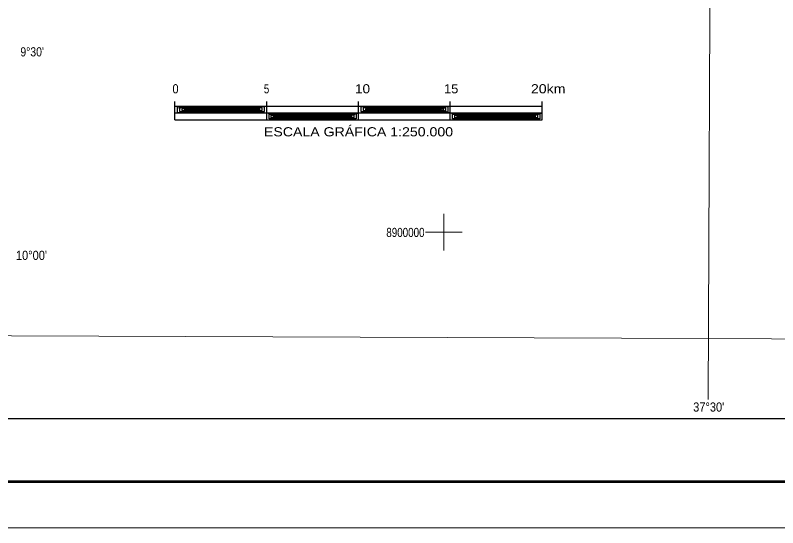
# Model space of a CAD drawing. Extents: x 553962 to 842807, y 8883888 to 9032388.
# Drawn here: x 626649 to 668185, y 8883888 to 8911837 of the extents above; entities that cross this region are included whole.
import ezdxf
from ezdxf.enums import TextEntityAlignment as Align

# ---------------------------------------------------------------- set-up
doc = ezdxf.new("R2010")
doc.units = 0
doc.header["$LTSCALE"] = 150
doc.header["$PDMODE"] = 32
doc.header["$PDSIZE"] = 75
for name, color, linetype, lineweight in [('1', 7, 'Continuous', 13), ('2', 7, 'Continuous', 13), ('3', 7, 'Continuous', 13), ('5', 7, 'Continuous', 25), ('6', 7, 'Continuous', 13)]:
    doc.layers.add(name, color=color, linetype=linetype, lineweight=lineweight)
doc.layers.add('46', color=7, linetype='Continuous')
doc.layers.add('47', color=7, linetype='Continuous')

msp = doc.modelspace()

# ---------------------------------------------------------------- linework, layer by layer
at = {"layer": '1'}
for points in [[(664968.2, 9023436.8), (664657.1, 8949509), (664397.1, 8890880.2)], [(564751.7, 8894587.5), (664411.9, 8894209.9), (791388.5, 8893536.2)]]:
    msp.add_lwpolyline(points, dxfattribs=at)
at = {"layer": '2'}
for p, q in [((650000, 8899000), (650000, 8901000)), ((649000, 8900000), (651000, 8900000))]:
    msp.add_line(p, q, dxfattribs=at)
at = {"layer": '3'}
msp.add_lwpolyline([(842807.3, 9032387.8), (842807.3, 8883887.8), (553961.7, 8883887.8), (553961.7, 9032387.8)], close=True, dxfattribs=at)
at = {"layer": '3', "lineweight": 53}
msp.add_lwpolyline([(840307.3, 9029887.8), (840307.3, 8886387.8), (560211.7, 8886387.8), (560211.7, 9029887.8)], close=True, dxfattribs=at)
at = {"layer": '3', "lineweight": 25}
msp.add_lwpolyline([(563033.9, 9026438.8), (793061.1, 9026438.8), (793495.6, 8889836.8), (563468.3, 8889836.8)], close=True, dxfattribs=at)
at = {"layer": '5'}
for p, q in [((635348.6, 8906137.1), (635348.6, 8907137.1)), ((640348.6, 8906137.1), (640348.6, 8907137.1)), ((645348.6, 8906137.1), (645348.6, 8907137.1)), ((650348.6, 8906137.1), (650348.6, 8907137.1)), ((655348.6, 8906137.1), (655348.6, 8907137.1)), ((635348.6, 8906887.1), (655348.6, 8906887.1)), ((635348.6, 8906513.1), (655348.6, 8906513.1)), ((635348.6, 8906137.1), (655348.6, 8906137.1))]:
    msp.add_line(p, q, dxfattribs=at)
msp.add_lwpolyline([(635848.6, 8906687.1), (639973.6, 8906687.1), (639973.6, 8906737.1), (635723.6, 8906737.1), (635723.6, 8906637.1), (640098.6, 8906637.1), (640098.6, 8906787.1), (635598.6, 8906787.1), (635598.6, 8906587.1), (640223.6, 8906587.1), (640223.6, 8906837.1), (635473.6, 8906837.1), (635473.6, 8906537.1), (640223.6, 8906537.1), (640348.6, 8906513.1), (640473.6, 8906487.1), (645223.6, 8906487.1), (645223.6, 8906187.1), (640473.6, 8906187.1), (640473.6, 8906437.1), (645098.6, 8906437.1), (645098.6, 8906237.1), (640598.6, 8906237.1), (640598.6, 8906387.1), (644973.6, 8906387.1), (644973.6, 8906287.1), (640723.6, 8906287.1), (640723.6, 8906337.1), (644848.6, 8906337.1), (645348.6, 8906513.1), (645473.6, 8906537.1), (650223.6, 8906537.1), (650223.6, 8906837.1), (645473.6, 8906837.1), (645473.6, 8906587.1), (650098.6, 8906587.1), (650098.6, 8906787.1), (645598.6, 8906787.1), (645598.6, 8906637.1), (649973.6, 8906637.1), (649973.6, 8906737.1), (645723.6, 8906737.1), (645723.6, 8906687.1), (649848.6, 8906687.1), (650348.6, 8906513.1), (650473.6, 8906487.1), (655223.6, 8906487.1), (655223.6, 8906187.1), (650473.6, 8906187.1), (650473.6, 8906437.1), (655098.6, 8906437.1), (655098.6, 8906237.1), (650598.6, 8906237.1), (650598.6, 8906387.1), (654973.6, 8906387.1), (654973.6, 8906287.1), (650723.6, 8906287.1), (650723.6, 8906337.1), (654848.6, 8906337.1), (655348.6, 8906513.1)], dxfattribs=at)
for p in [(635598.6, 8906787.1), (649973.6, 8906762.1), (649973.6, 8906637.1)]:
    msp.add_point(p, dxfattribs=at)

# ---------------------------------------------------------------- texts
at = {"layer": '46', "width": 0.9}
msp.add_text("37°30'", height=500, dxfattribs=at).set_placement((664424.4, 8890221.9), align=Align.CENTER)
at = {"layer": '47', "width": 0.8}
msp.add_text('8900000', height=500, dxfattribs=at).set_placement((647902.6, 8899742), align=Align.CENTER)
at = {"layer": '5'}
for s, width, p in [('0', 0.9, (635212.5, 8907577.2)), ('5', 0.8, (640189, 8907577.2)), ('10', 1.1, (645158.2, 8907577.2)), ('15', 1.05, (650004, 8907577.2)), ('20km', 1.15, (654740, 8907577.2))]:
    msp.add_text(s, height=500, dxfattribs=dict(at, width=width)).set_placement(p)
at = {"layer": '5', "width": 1.15}
msp.add_text('ESCALA GRÁFICA 1:250.000', height=500, dxfattribs=at).set_placement((645348.5, 8905230.5), align=Align.CENTER)
at = {"layer": '6'}
for s, width, p in [("9°30'", 0.85, (627569.2, 8909591.6)), ("10°00'", 0.9, (627532, 8898493.5))]:
    msp.add_text(s, height=500, dxfattribs=dict(at, width=width)).set_placement(p, align=Align.CENTER)

doc.saveas('drawing.dxf')
